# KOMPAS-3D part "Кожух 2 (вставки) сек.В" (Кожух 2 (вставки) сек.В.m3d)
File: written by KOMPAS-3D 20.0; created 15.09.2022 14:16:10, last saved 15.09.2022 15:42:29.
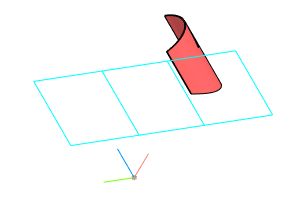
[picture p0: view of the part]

Document properties: Полное имя файла: D:\YAKOVLEV\ПРОЕКТЫ\ДЦ-2. ДП-7 Газопровод Окожушивание\ПРОБА Соединение труб. Окожушивание\Кожух 2 (вставки) сек.В.m3d

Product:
- Part/product: Кожух 2 (вставки) сек.В
    Материал: Сталь 45  ГОСТ 1050-2013 (density 7810 kg/m3)
    Масса: 153.628

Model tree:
1. Эскиз:1  (with: Смещенная плоскость:1, Обечайка:1)  (labels: Кожух 2 (вставки))
2. Обечайка:1  (labels: Кожух 1 (трубы); Кожух 2 (вставки))
     Расстояние 1 = 823.908
3. Сгиб(1) - Обечайка:1
     Радиус сгиба = 530; Коэффициент = 0.5; Величина сгиба = 10; Зазор = 0.01; Угол = 180; Параметр U, % = 11; Длина = 366.31
4. Касательная плоскость:1  (with: Обечайка:1)
5. Разогнуть:1  (with: Обечайка:1)
6. Смещенная плоскость:1  (with: Обечайка:1)
     Расстояние = 0.1
7. Эскиз:3  (with: Обечайка:1)
8. Вырез в листовом теле:3
     Глубина выреза = 100
9. Элемент выдавливания:1
     Расстояние 2 = 20
10. Эскиз:4  (with: Обечайка:1, Вырез в листовом теле:3)
11. Вырез в листовом теле:4
     Глубина выреза = 100
12. Эскиз:5  (with: Обечайка:1)
13. Вырез в листовом теле:5
     Глубина выреза = 10
14. Эскиз:6  (with: Обечайка:1)
15. Вырез в листовом теле:6
     Глубина выреза = 0.1
16. Фаска:1  (with: Обечайка:1, Вырез в листовом теле:5)
     Угол = 20; Длина 1 = 14; Длина 2 = 5.09558
17. Согнуть:1  (with: Обечайка:1)
18. Развертка  (labels: Сталь 45  ГОСТ 1050-2013)

Expressions: v172*2
Referenced files in D:\YAKOVLEV\ПРОЕКТЫ\ДЦ-2. ДП-7 Газопровод Окожушивание\ПРОБА Соединение труб. Окожушивание\: Соединение труб. Окожушивание -2.a3d
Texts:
  Соединение труб. Окожушивание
